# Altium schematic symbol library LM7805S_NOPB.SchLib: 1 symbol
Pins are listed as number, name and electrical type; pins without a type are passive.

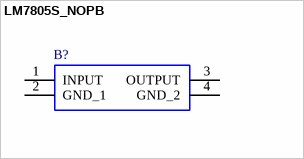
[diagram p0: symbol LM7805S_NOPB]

## LM7805S_NOPB
designator B?
1.5-A, Wide VIN Fixed Voltage Regulators; Manufacturer_Name: Texas Instruments; Manufacturer_Part_Number: LM7805S/NOPB
footprint KTT0003B
pins: 1 INPUT, 2 GND_1, 3 OUTPUT, 4 GND_2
